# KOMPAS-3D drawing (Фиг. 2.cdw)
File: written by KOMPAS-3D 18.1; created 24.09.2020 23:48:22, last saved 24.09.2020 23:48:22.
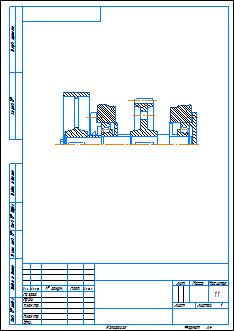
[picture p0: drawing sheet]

Sheet 1: A4, portrait

Document properties: Автор: user; Полное имя файла: C:\Users\user\Desktop\Задания\Фиг. 2.cdw

Title block, sheet 1: scale: 1:1; Количество листов документа: 1; Форматы листов документа: A4

Dimensions and other numbers on the sheet: 1:1; 1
